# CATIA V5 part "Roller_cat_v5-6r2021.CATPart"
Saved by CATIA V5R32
Part number: Roller
Bounding box of the stored display mesh (mm): x 0 to 20, y -10 to 10, z -10 to 10
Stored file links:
  D:\PROJECTS\Project 2022\CATIA V5 6R 2022\Resources\Tutorial Files\c16_catia_v5_6r2022_tut\Bearing\Roller_cat_v5-6r2021.CATPart
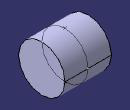
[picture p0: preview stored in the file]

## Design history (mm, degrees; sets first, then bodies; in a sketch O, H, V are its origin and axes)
Body1 (main body)
  Sketch1 on yz-plane, origin (0, 0, 0), H (0, 1, 0), V (0, 0, 1)
    circle A1 centre (0, 0) radius 10
    radius A1 = 10
  Pad1: profile Sketch1, direction (1, 0, 0), length 20
  Plane1: type Offset, RefPlane end face of Pad1, Offset -10, reversed
  Sketch2 on Plane1, origin (10, 0, 0), H (0, -1, 0), V (0, 0, 1)
    projected circle E1 centre (0, 0) radius 10 from edge [face of Pad1 from Sketch1.A1 | end face of Pad1]
    point P1 (0, -10)
    point P2 (0, 10)
    coincidence: P1 E1, P1 V, P2 V, E1 P2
